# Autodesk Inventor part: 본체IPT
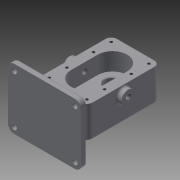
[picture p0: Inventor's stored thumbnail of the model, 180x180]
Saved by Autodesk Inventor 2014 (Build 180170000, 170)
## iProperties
Created: 2020-04
Part Number: 본체IPT
Material: Generic
Document SubType Name: Modeling
Designer: kh
Density: 1 g/cm^3
Appearance: Default
Author: kh
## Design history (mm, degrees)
sketch "스케치1"
  geometry: L1 (-40, -60)-(40, -60); L2 (40, -60)-(40, 60); L3 (40, 60)-(-40, 60); L4 (-40, 60)-(-40, -60); L5 (-40, -60)-(40, 60); L6 (40, -60)-(-40, 60); 1 further point
  constraints: 12 end point, 2 midpoint, 2 parallel, 1 horizontal, 1 perpendicular
  dimensions: "d0" = 80 distance of L2.end L3.end; "d1" = 120 distance between parallel lines of L1 L3
extrude "돌출1" new body sketch "스케치1" distance "d2" = 53; taper "d3" = 0 deg
sketch "스케치2"
  geometry: L1 (40, 60)-(-40, 60) reference; L2 (-40, -60)-(40, -60) reference; L3 (0, 22)-(0, -22); L4 (-24, 22)-(-24, -22); L5 (24, -22)-(24, 22); A1 r 24 centre (0, 22) between (24, 22) and (-24, 22); A2 r 24 centre (0, -22) between (-24, -22) and (24, -22); 3 further points
  constraints: 8 end point, 4 point on circle, 4 tangent, 2 centre point, 2 coincident, 1 midpoint, 1 parallel, 1 perpendicular
  dimensions: "d8" = 44 distance of L3.end L3.start; "d9" = 24 radius of A2
extrude "돌출2" cut sketch "스케치2" distance "d10" = 29; taper "d11" = 0 deg
sketch "스케치3"
  geometry: L1 (0, 0)-(0, 22); L2 (0, 0)-(0, -22); C1 r 12.5 at (0, 22); C2 r 12.5 at (0, -22)
  constraints: 4 end point, 2 centre point, 2 coincident, 1 collinear, 1 vertical
  dimensions: "d12" = 22 distance of L1.start L1.end; "d13" = 22 distance of L1.start L2.end; "d14" = 25 diameter of C1; "d15" = 25 diameter of C2
extrude "돌출3" cut sketch "스케치3" distance "d16" = 15; taper "d17" = 0 deg
sketch "스케치4"
  geometry: C1 r 19 at (0, 22); A1 r 24 centre (0, 22) between (24, 22) and (-24, 22) reference; 1 further point
  constraints: 1 centre point, 1 coincident
  dimensions: "d18" = 38 diameter of C1
extrude "돌출4" join sketch "스케치4" distance "d19" = 17; taper "d20" = 0 deg
sketch "스케치5"
  geometry: C1 r 19 at (0, 0) reference; C2 r 14 at (0, 0); 1 further point
  constraints: 1 centre point, 1 coincident
  dimensions: "d21" = 28 diameter of C2
extrude "돌출5" cut sketch "스케치5" distance "d22" = 7.3; taper "d23" = 0 deg
sketch "스케치6"
  geometry: C1 r 14 at (0, 0) reference; C2 r 8.5 at (0, 0); 1 further point
  constraints: 1 centre point, 1 coincident
  dimensions: "d24" = 17 diameter of C2
extrude "돌출6" cut sketch "스케치6" stored distance "d25" = 17 (= d24); taper "d26" = 0 deg
sketch "스케치7"
  geometry: L1 (0, 60)-(-39, 60); L2 (-53, 0)-(-53, 120) reference; C1 r 11 at (-39, 60)
  constraints: 2 end point, 1 centre point, 1 coincident, 1 horizontal
  dimensions: "d27" = 14 distance from line of L1.end L2; "d28" = 22 diameter of C1
extrude "돌출7" join sketch "스케치7" distance "d29" = 8; taper "d30" = 0 deg
hole "구멍1" diameter "d33" = 8.917; stored, may be unused: countersink angle "d37" = 90 deg, drill point angle "d39" = 118 deg; dims "d34" = 100, "d35" = 4, "d36" = 2, "d38" = 8, "d40" = 10, "d41" = 10
sketch "스케치8"
  geometry: C1 r 4.458 at (39, 60) reference; C2 r 11 at (39, 60); 1 further point
  constraints: 1 centre point, 1 coincident
  dimensions: "d42" = 22 diameter of C2
extrude "돌출8" join sketch "스케치8" distance "d43" = 8; taper "d44" = 0 deg
fillet "모깎기1" dims "d45" = 3
node "작업 평면1"
sketch "스케치9"
  geometry: L1 (-19, -17)-(19, -17) reference; L2 (-50, -17)-(50, -17); L3 (60, -7)-(60, 73); L4 (50, 83)-(-50, 83); L5 (-60, 73)-(-60, -7); C1 r 4.5 at (50, 73); C2 r 4.5 at (50, -7); C3 r 4.5 at (-50, -7); C4 r 4.5 at (-50, 73); A1 r 10 centre (50, 73) between (60, 73) and (50, 83); A2 r 10 centre (50, -7) between (50, -17) and (60, -7); A3 r 10 centre (-50, -7) between (-60, -7) and (-50, -17); A4 r 10 centre (-50, 73) between (-50, 83) and (-60, 73); 5 further points
  constraints: 8 centre point, 8 end point, 8 point on circle, 8 tangent, 6 point on line, 4 coincident, 3 equal radius, 2 midpoint, 2 parallel, 1 horizontal, 1 perpendicular
  dimensions: "d47" = 100 distance of point (60, -17) point (60, 83); "d48" = 120 distance of point (60, 83) point (-60, 83); "d49" = 10 radius of A1; "d50" = 9 diameter of C1; "d51" = 9 diameter of C2; "d52" = 9 diameter of C3; "d53" = 9 diameter of C4
extrude "돌출9" join sketch "스케치9" distance "d54" = 10; taper "d55" = 0 deg
sketch "스케치10"
  geometry: L1 (60, -73)-(60, 7) reference; L2 (-60, 7)-(-60, -73) reference; L3 (50, 17)-(-50, 17) reference; L4 (-50, -83)-(50, -83) reference; L5 (0, 17)-(0, -83); L6 (24, -37)-(-24, -37); L7 (-24, -37)-(-24, -17); L8 (-24, -17)-(24, -17); L9 (24, -17)-(24, -37); L10 (24, -37)-(-24, -17); L11 (-24, -37)-(24, -17); 3 further points
  constraints: 14 end point, 5 midpoint, 2 parallel, 1 horizontal, 1 perpendicular, 1 point on line
  dimensions: "d64" = 17 distance from line of point (0, 0) L8; "d65" = 48 distance of L6.start L6.end; "d66" = 20 distance of L8.end L6.start
sketch "스케치11"
  geometry: L1 (-80, 73)-(-80, -7) reference; L2 (-80, 53)-(-68.965, 46.629); L3 (-80, 0)-(-64.027, 9.222); L4 (0, 53)-(-60, 53) reference; L5 (60, 0)-(-60, 0) reference; L6 (0, 0)-(-23.702, 0); L7 (0, 53)-(-16.183, 53); L8 (-60, 0)-(-80, 0); L9 (-60, 53)-(-80, 53); L10 (-80, 53)-(-80, 0)
  constraints: 14 end point, 4 point on line, 3 perpendicular
  dimensions: "d62" = 60 deg angle of L1 L3; "d63" = 60 deg angle of L1 L2
extrude "돌출12" join sketch "스케치10" stored distance "d67" = 10; taper "d68" = 0 deg
feature "리브1" dims "d69" = 1, "d70" = 48, "d71" = 0, "d72" = 0, "d73" = 1, "d74" = 1
node "작업 평면2"
fillet "모깎기2" dims "d75" = 9
sketch "스케치12"
  geometry: L1 (-31, 51)-(31, 51); L2 (31, 51)-(31, 22); L3 (31, 22)-(-31, 22); L4 (-31, 22)-(-31, 51); L5 (-31, -22)-(31, -22); L6 (31, -22)-(31, -51); L7 (31, -51)-(-31, -51); L8 (-31, -51)-(-31, -22); C1 r 8.5 at (0, 22) reference; C2 r 12.5 at (0, -22) reference; 11 further points
  constraints: 16 end point, 10 coincident, 4 parallel, 2 horizontal, 2 midpoint, 2 perpendicular
  dimensions: "d76" = 29 distance of L1.end L2.end; "d77" = 62 distance of L1.start L1.end; "d78" = 29 distance of L5.end L6.end; "d79" = 62 distance of L6.end L7.end
hole "구멍2" sketch "스케치12" at (31, 22), (31, 51), (-31, 51), (-31, 22), (31, -22), (31, -51), (-31, -51), (-31, -22) diameter "d80" = 4.459; stored, may be unused: countersink angle "d84" = 90 deg, drill point angle "d86" = 118 deg; dims "d81" = 10, "d82" = 4, "d83" = 2, "d85" = 12
chamfer "모따기1" distance "d87" = 1; stored, may be unused: second distance "d88" = 2, angle "d89" = 45 deg
chamfer "모따기2" distance "d90" = 1; stored, may be unused: second distance "d91" = 2, angle "d92" = 45 deg
fillet "모깎기3" dims "d93" = 0.5
chamfer "모따기3" distance "d94" = 0.7; stored, may be unused: second distance "d95" = 2, angle "d96" = 30 deg
sketch "스케치13"
  geometry: L1 (-43.403, -70.186)-(43.403, -70.186); L2 (43.403, -70.186)-(43.403, -75.814); L3 (43.403, -75.814)-(-43.403, -75.814); L4 (-43.403, -75.814)-(-43.403, -70.186); L5 (-43.403, -73)-(43.403, -73); L6 (0, -75.814)-(0, -70.186); L7 (-50, -83)-(50, -83) reference; L8 (-60, 7)-(-60, -73) reference; 1 further point
  constraints: 4 end point, 4 midpoint, 2 other
  dimensions: "d97" = 10 distance between parallel lines of L7 L5; "d98" = 60 distance between parallel lines of L8 L6
feature "엠보싱1" sketch "스케치13" dims "d0" = 80, "d1" = 120, "d99" = 0.5, "d100" = 0
fillet "모깎기4" dims "d101" = 3
fillet "모깎기5" dims "d102" = 3
fillet "모깎기6" dims "d103" = 3
fillet "모깎기7" dims "d104" = 3
node "솔리드1"
mirror "대칭1"
